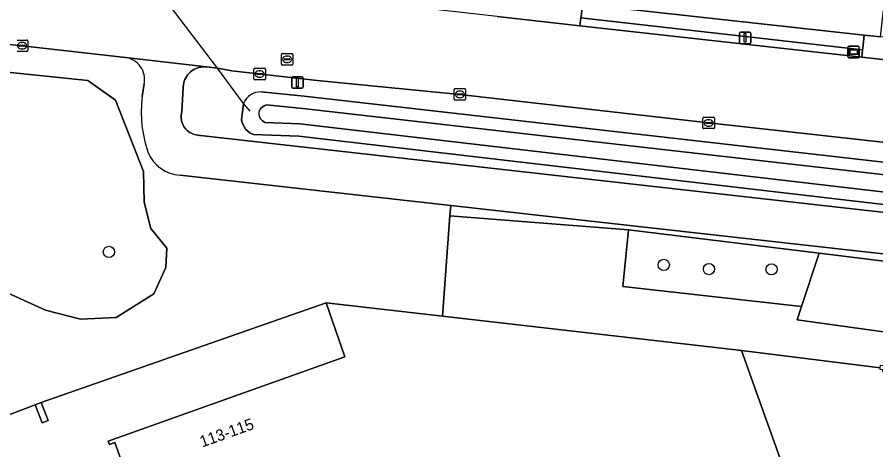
# Model space of a CAD drawing. Extents: x 161385 to 162589, y 388479 to 389756.
# Drawn here: x 162174.2 to 162249.2, y 388654.2 to 388691.9 of the extents above; entities that cross this region are included whole.
import ezdxf

# ---------------------------------------------------------------- set-up
doc = ezdxf.new("R2010")
doc.units = 0
for name, color, linetype in [('IMGEO_Berm_groen', 7, 'Continuous'), ('IMGEO_Boom', 7, 'Continuous'), ('IMGEO_Duiker', 7, 'Continuous'), ('IMGEO_Erf', 7, 'Continuous'), ('IMGEO_Fietspad_gesloten', 7, 'Continuous'), ('IMGEO_Groenvoorziening', 7, 'Continuous'), ('IMGEO_Kolk', 7, 'Continuous'), ('IMGEO_Lichtmast', 7, 'Continuous'), ('IMGEO_Oever', 7, 'Continuous'), ('IMGEO_Pand', 7, 'Continuous'), ('IMGEO_Pand_nummerreeks', 7, 'Continuous'), ('IMGEO_Rijbaan_lokaal_gesloten', 7, 'Continuous'), ('IMGEO_Rioolput', 7, 'Continuous'), ('IMGEO_Voetpad_open', 7, 'Continuous'), ('IMGEO_Waterloop', 7, 'Continuous'), ('IMGEO_Wegwijzer', 7, 'Continuous')]:
    doc.layers.add(name, color=color, linetype=linetype)

msp = doc.modelspace()

# ---------------------------------------------------------------- linework, layer by layer
at = {"layer": 'IMGEO_Berm_groen'}
for points in [[(162223.419, 388691.863), (162223.34, 388691.176), (162247.951, 388688.424), (162248.018, 388689.075)], [(162212.05, 388675.493), (162211.982, 388674.58), (162227.587, 388673.375), (162244.211, 388671.327), (162267.366, 388668.474), (162328.021, 388661.404), (162328.163, 388662.672), (162327.44, 388662.75), (162327.383, 388662.532), (162314.863, 388664.007)]]:
    msp.add_lwpolyline(points, close=True, dxfattribs=at)
for points in [[(162256.569, 388680.26), (162234.573, 388682.697), (162212.852, 388685.186), (162200.409, 388686.41), (162192.948, 388687.248), (162191.691, 388687.487), (162190.731, 388687.591), (162190.565, 388687.6), (162190.4, 388687.594), (162190.235, 388687.573), (162190.073, 388687.537), (162189.915, 388687.488), (162189.762, 388687.424), (162189.615, 388687.347), (162189.476, 388687.257), (162189.345, 388687.155), (162189.224, 388687.041), (162189.113, 388686.918), (162189.014, 388686.785), (162188.927, 388686.643), (162188.854, 388686.495), (162188.794, 388686.34), (162188.747, 388686.181), (162188.716, 388686.018), (162188.699, 388685.853), (162188.696, 388685.79), (162188.57, 388683.655), (162188.54, 388683.511), (162188.523, 388683.366), (162188.52, 388683.219), (162188.529, 388683.073), (162188.552, 388682.928), (162188.587, 388682.786), (162188.635, 388682.647), (162188.695, 388682.513), (162188.766, 388682.385), (162188.849, 388682.265), (162188.943, 388682.151), (162189.046, 388682.047), (162189.158, 388681.953), (162189.278, 388681.868), (162189.405, 388681.795), (162189.538, 388681.734), (162189.676, 388681.684), (162189.818, 388681.647), (162189.962, 388681.623), (162190.109, 388681.612), (162190.209, 388681.612), (162327.081, 388666.21)], [(162195.511, 388685.399), (162199.258, 388685.044), (162309.372, 388672.493), (162313.677, 388672.019)], [(162314.929, 388670.455), (162314.838, 388669.228), (162314.739, 388669.003), (162314.316, 388668.451), (162313.561, 388668.026), (162313.044, 388667.945), (162308.893, 388668.677), (162198.797, 388681.534), (162194.824, 388681.685), (162194.516, 388681.817), (162194.124, 388682.146), (162193.837, 388682.714), (162193.797, 388682.968), (162193.974, 388684.393)]]:
    msp.add_lwpolyline(points, dxfattribs=at)
msp.add_arc((162195.451, 388683.814), 1.587, 87.83194, 158.5793, dxfattribs=at)
at = {"layer": 'IMGEO_Boom'}
for centre in [(162182.211, 388671.44), (162230.659, 388670.305), (162234.598, 388669.941), (162240.061, 388669.921)]:
    msp.add_circle(centre, 0.489, dxfattribs=at)
at = {"layer": 'IMGEO_Duiker'}
msp.add_lwpolyline([(162194.552, 388683.711), (162193.974, 388684.393), (162191.691, 388687.487), (162185.651, 388695.455)], dxfattribs=at)
at = {"layer": 'IMGEO_Erf'}
for points in [[(162185.543, 388646.914), (162182.743, 388654.798), (162182.252, 388654.637), (162182.158, 388654.923), (162202.802, 388662.297), (162201.171, 388666.993), (162176.301, 388658.294), (162176.903, 388656.724), (162176.388, 388656.526), (162175.785, 388658.097), (162170.991, 388656.301), (162170.064, 388658.999), (162164.277, 388656.982), (162154.98, 388683.469), (162154.569, 388683.938), (162154.062, 388683.782), (162156.404, 388677.209), (162139.153, 388671.976), (162153.607, 388624.128)], [(162278.169, 388581.632), (162249.791, 388661.103), (162249.773, 388661.153), (162249.539, 388661.179), (162249.555, 388661.32), (162237.455, 388662.849), (162248.797, 388631.105)]]:
    msp.add_lwpolyline(points, dxfattribs=at)
at = {"layer": 'IMGEO_Fietspad_gesloten'}
for points in [[(162327.081, 388666.21), (162190.209, 388681.612), (162190.109, 388681.612), (162189.962, 388681.623), (162189.818, 388681.647), (162189.676, 388681.684), (162189.538, 388681.734), (162189.405, 388681.795), (162189.278, 388681.868), (162189.158, 388681.953), (162189.046, 388682.047), (162188.943, 388682.151), (162188.849, 388682.265), (162188.766, 388682.385), (162188.695, 388682.513), (162188.635, 388682.647), (162188.587, 388682.786), (162188.552, 388682.928), (162188.529, 388683.073), (162188.52, 388683.219), (162188.523, 388683.366), (162188.54, 388683.511), (162188.57, 388683.655), (162188.696, 388685.79), (162188.699, 388685.853), (162188.716, 388686.018), (162188.747, 388686.181), (162188.794, 388686.34), (162188.854, 388686.495), (162188.927, 388686.643), (162189.014, 388686.785), (162189.113, 388686.918), (162189.224, 388687.041), (162189.345, 388687.155), (162189.476, 388687.257), (162189.615, 388687.347), (162189.762, 388687.424), (162189.915, 388687.488), (162190.073, 388687.537), (162190.235, 388687.573), (162190.4, 388687.594), (162190.565, 388687.6), (162190.731, 388687.591), (162183.657, 388688.405)], [(162185.28, 388686.094), (162185.128, 388685.009)], [(162188.441, 388678.131), (162212.05, 388675.493), (162314.863, 388664.007), (162327.383, 388662.532), (162327.44, 388662.75), (162328.163, 388662.672), (162328.425, 388662.644)]]:
    msp.add_lwpolyline(points, dxfattribs=at)
for centre, radius, start, end in [((162183.403, 388686.501), 1.92, 347.74902, 82.4112), ((162195.589, 388683.618), 10.553, 172.42806, 199.06817), ((162188.627, 388681.366), 3.241, 201.64367, 266.70768)]:
    msp.add_arc(centre, radius, start, end, dxfattribs=at)
at = {"layer": 'IMGEO_Groenvoorziening'}
for points in [[(162249.57, 388690.204), (162249.919, 388693.319), (162223.633, 388696.259), (162223.374, 388693.364), (162223.587, 388693.331), (162223.557, 388693.066), (162248.149, 388690.348)], [(162164.533, 388675.08), (162172.104, 388668.423), (162176.667, 388666.349), (162179.722, 388665.557), (162182.852, 388665.708), (162186.133, 388667.782), (162187.189, 388670.082), (162187.264, 388671.779), (162185.869, 388673.476), (162185.303, 388675.776), (162185.228, 388678.454), (162182.776, 388684.676), (162180.363, 388686.411), (162171.048, 388687.354), (162167.504, 388687.618), (162164.223, 388686.562), (162163.648, 388686.001), (162162.196, 388681.874)], [(162266.988, 388662.085), (162242.291, 388665.501), (162242.681, 388666.67), (162227.085, 388668.43), (162227.587, 388673.375), (162211.982, 388674.58), (162211.331, 388665.832), (162237.455, 388662.849), (162249.555, 388661.32), (162249.582, 388661.569), (162250.099, 388661.511), (162324.031, 388653.194), (162323.903, 388652.051), (162326.935, 388651.71), (162327.291, 388654.887), (162309.928, 388656.723)], [(162242.681, 388666.67), (162244.211, 388671.327), (162227.587, 388673.375), (162227.085, 388668.43)], [(162266.988, 388662.085), (162309.928, 388656.723), (162327.291, 388654.887), (162328.021, 388661.404), (162267.366, 388668.474), (162244.211, 388671.327), (162242.681, 388666.67), (162242.291, 388665.501)]]:
    msp.add_lwpolyline(points, close=True, dxfattribs=at)
for points in [[(162183.657, 388688.405), (162174.63, 388689.431), (162165.201, 388690.414)], [(162171.048, 388687.354), (162180.363, 388686.411), (162182.776, 388684.676), (162185.228, 388678.454), (162185.303, 388675.776), (162185.869, 388673.476), (162187.264, 388671.779), (162187.189, 388670.082), (162186.133, 388667.782), (162182.852, 388665.708), (162179.722, 388665.557), (162176.667, 388666.349), (162172.104, 388668.423)], [(162185.128, 388685.009), (162185.28, 388686.094)], [(162170.991, 388656.301), (162175.785, 388658.097), (162176.301, 388658.294), (162201.171, 388666.993), (162211.331, 388665.832), (162211.982, 388674.58), (162212.05, 388675.493), (162188.441, 388678.131)]]:
    msp.add_lwpolyline(points, dxfattribs=at)
for centre, radius, start, end in [((162183.403, 388686.501), 1.92, 347.74902, 82.4112), ((162195.589, 388683.618), 10.553, 172.42806, 199.06817), ((162188.627, 388681.366), 3.241, 201.64367, 266.70768)]:
    msp.add_arc(centre, radius, start, end, dxfattribs=at)
at = {"layer": 'IMGEO_Kolk'}
for p, q in [((162174.204, 388689.93), (162175.056, 388689.93)), ((162174.617, 388689.71), (162174.642, 388689.71)), ((162175.13, 388689.856), (162175.13, 388689.004)), ((162175.056, 388688.93), (162174.204, 388688.93)), ((162174.388, 388689.424), (162174.388, 388689.436)), ((162174.826, 388689.387), (162174.428, 388689.387)), ((162174.431, 388689.473), (162174.829, 388689.473)), ((162174.64, 388689.15), (162174.615, 388689.15)), ((162174.872, 388689.436), (162174.872, 388689.424)), ((162194.948, 388687.47), (162195.8, 388687.47)), ((162194.873, 388686.544), (162194.873, 388687.396)), ((162195.132, 388686.964), (162195.132, 388686.976)), ((162195.57, 388686.927), (162195.172, 388686.927)), ((162195.175, 388687.013), (162195.573, 388687.013)), ((162195.384, 388686.69), (162195.359, 388686.69)), ((162195.361, 388687.25), (162195.386, 388687.25)), ((162195.616, 388686.976), (162195.616, 388686.964)), ((162195.874, 388687.396), (162195.874, 388686.544)), ((162195.8, 388686.47), (162194.948, 388686.47)), ((162212.35, 388684.76), (162212.35, 388685.612)), ((162212.425, 388685.686), (162213.277, 388685.686)), ((162212.609, 388685.18), (162212.609, 388685.192)), ((162212.652, 388685.229), (162213.05, 388685.229)), ((162212.838, 388685.466), (162212.863, 388685.466)), ((162213.093, 388685.192), (162213.093, 388685.18)), ((162213.351, 388685.612), (162213.351, 388684.76)), ((162213.277, 388684.686), (162212.425, 388684.686)), ((162213.047, 388685.143), (162212.649, 388685.143)), ((162212.861, 388684.906), (162212.836, 388684.906)), ((162234.072, 388682.27), (162234.072, 388683.122)), ((162234.147, 388683.196), (162234.999, 388683.196)), ((162234.56, 388682.976), (162234.585, 388682.976)), ((162235.073, 388683.122), (162235.073, 388682.27)), ((162234.999, 388682.196), (162234.147, 388682.196)), ((162234.331, 388682.69), (162234.331, 388682.702)), ((162234.769, 388682.653), (162234.371, 388682.653)), ((162234.374, 388682.739), (162234.772, 388682.739)), ((162234.583, 388682.416), (162234.558, 388682.416)), ((162234.815, 388682.702), (162234.815, 388682.69))]:
    msp.add_line(p, q, dxfattribs=at)
for points in [[(162174.204, 388689.93), (162175.056, 388689.93)], [(162175.13, 388689.856), (162175.13, 388689.004)], [(162175.056, 388688.93), (162174.204, 388688.93)], [(162194.948, 388687.47), (162195.8, 388687.47)], [(162194.873, 388686.544), (162194.873, 388687.396)], [(162195.874, 388687.396), (162195.874, 388686.544)], [(162195.8, 388686.47), (162194.948, 388686.47)], [(162212.35, 388684.76), (162212.35, 388685.612)], [(162212.425, 388685.686), (162213.277, 388685.686)], [(162213.351, 388685.612), (162213.351, 388684.76)], [(162213.277, 388684.686), (162212.425, 388684.686)], [(162234.072, 388682.27), (162234.072, 388683.122)], [(162234.147, 388683.196), (162234.999, 388683.196)], [(162235.073, 388683.122), (162235.073, 388682.27)], [(162234.999, 388682.196), (162234.147, 388682.196)]]:
    msp.add_lwpolyline(points, dxfattribs=at)
for centre, radius, start, end in [((162175.054, 388689.854), 0.0765, 1.55205, 88.44795), ((162175.054, 388689.854), 0.0765, 1.55205, 88.44795), ((162174.428, 388689.433), 0.0403, 85.87752, 175.75265), ((162174.425, 388689.423), 0.0366, 178.93798, 274.71019), ((162174.829, 388689.43), 0.043, 264.86636, 352.45326), ((162174.833, 388689.435), 0.0386, 1.73085, 96.63898), ((162175.054, 388689.006), 0.0765, 271.55205, 358.44795), ((162175.054, 388689.006), 0.0765, 271.55205, 358.44795), ((162194.95, 388687.394), 0.0765, 91.55205, 178.44795), ((162194.95, 388687.394), 0.0765, 91.55205, 178.44795), ((162195.798, 388687.394), 0.0765, 1.55205, 88.44795), ((162195.798, 388687.394), 0.0765, 1.55205, 88.44795), ((162195.172, 388686.973), 0.0403, 85.87752, 175.75265), ((162195.169, 388686.963), 0.0366, 178.93798, 274.71019), ((162195.573, 388686.97), 0.043, 264.86636, 352.45326), ((162195.577, 388686.975), 0.0386, 1.73085, 96.63898), ((162194.95, 388686.546), 0.0765, 181.55205, 268.44795), ((162194.95, 388686.546), 0.0765, 181.55205, 268.44795), ((162195.798, 388686.546), 0.0765, 271.55205, 358.44795), ((162195.798, 388686.546), 0.0765, 271.55205, 358.44795), ((162212.427, 388685.61), 0.0765, 91.55205, 178.44795), ((162212.427, 388685.61), 0.0765, 91.55205, 178.44795), ((162212.649, 388685.189), 0.0403, 85.87752, 175.75265), ((162212.646, 388685.179), 0.0366, 178.93798, 274.71019), ((162213.05, 388685.186), 0.043, 264.86636, 352.45326), ((162213.054, 388685.191), 0.0386, 1.73085, 96.63898), ((162213.275, 388685.61), 0.0765, 1.55205, 88.44795), ((162213.275, 388685.61), 0.0765, 1.55205, 88.44795), ((162212.427, 388684.762), 0.0765, 181.55205, 268.44795), ((162212.427, 388684.762), 0.0765, 181.55205, 268.44795), ((162213.275, 388684.762), 0.0765, 271.55205, 358.44795), ((162213.275, 388684.762), 0.0765, 271.55205, 358.44795), ((162234.149, 388683.12), 0.0765, 91.55205, 178.44795), ((162234.149, 388683.12), 0.0765, 91.55205, 178.44795), ((162234.997, 388683.12), 0.0765, 1.55205, 88.44795), ((162234.997, 388683.12), 0.0765, 1.55205, 88.44795), ((162234.149, 388682.272), 0.0765, 181.55205, 268.44795), ((162234.149, 388682.272), 0.0765, 181.55205, 268.44795), ((162234.371, 388682.699), 0.0403, 85.87752, 175.75265), ((162234.368, 388682.689), 0.0366, 178.93798, 274.71019), ((162234.772, 388682.696), 0.043, 264.86636, 352.45326), ((162234.776, 388682.701), 0.0386, 1.73085, 96.63898), ((162234.997, 388682.272), 0.0765, 271.55205, 358.44795), ((162234.997, 388682.272), 0.0765, 271.55205, 358.44795)]:
    msp.add_arc(centre, radius, start, end, dxfattribs=at)
for centre, major_axis, ratio, start_param, end_param in [((162174.616, 388689.43), (-0.387, 0.002), 0.722429, 4.712389, 7.853982), ((162174.641, 388689.43), (-0.39, 0.002), 0.717154, 1.570796, 4.712389), ((162195.36, 388686.97), (-0.387, 0.002), 0.722429, 4.712389, 7.853982), ((162195.385, 388686.97), (-0.39, 0.002), 0.717154, 1.570796, 4.712389), ((162212.837, 388685.186), (-0.387, 0.002), 0.722429, 4.712389, 7.853982), ((162212.862, 388685.186), (-0.39, 0.002), 0.717154, 1.570796, 4.712389), ((162234.559, 388682.696), (-0.387, 0.002), 0.722429, 4.712389, 7.853982), ((162234.584, 388682.696), (-0.39, 0.002), 0.717154, 1.570796, 4.712389)]:
    msp.add_ellipse(centre, major_axis=major_axis, ratio=ratio, start_param=start_param, end_param=end_param, dxfattribs=at)
at = {"layer": 'IMGEO_Lichtmast'}
for p, q in [((162237.254, 388689.71), (162237.254, 388690.51)), ((162237.254, 388690.51), (162237.254, 388689.71)), ((162237.354, 388690.61), (162238.144, 388690.61)), ((162238.144, 388690.61), (162237.354, 388690.61)), ((162238.244, 388690.51), (162238.244, 388689.71)), ((162238.244, 388689.71), (162238.244, 388690.51)), ((162238.144, 388689.61), (162237.354, 388689.61)), ((162237.354, 388689.61), (162238.144, 388689.61)), ((162198.274, 388686.715), (162199.064, 388686.715)), ((162199.064, 388686.715), (162198.274, 388686.715)), ((162198.174, 388685.815), (162198.174, 388686.615)), ((162198.174, 388686.615), (162198.174, 388685.815)), ((162199.164, 388686.615), (162199.164, 388685.815)), ((162199.164, 388685.815), (162199.164, 388686.615)), ((162199.064, 388685.715), (162198.274, 388685.715)), ((162198.274, 388685.715), (162199.064, 388685.715))]:
    msp.add_line(p, q, dxfattribs=at)
for points in [[(162237.674, 388690.485), (162237.824, 388690.485), (162237.824, 388689.735), (162237.674, 388689.735), (162237.674, 388690.485)], [(162198.594, 388686.59), (162198.744, 388686.59), (162198.744, 388685.84), (162198.594, 388685.84), (162198.594, 388686.59)]]:
    msp.add_lwpolyline(points, dxfattribs=at)
for centre, start, end in [((162237.354, 388690.51), 90, 180), ((162237.354, 388690.51), 90, 180), ((162238.144, 388690.51), 0, 90), ((162238.144, 388690.51), 360, 90), ((162237.354, 388689.71), 180, 270), ((162237.354, 388689.71), 180, 270), ((162238.144, 388689.71), 270, 0), ((162238.144, 388689.71), 270, 0), ((162198.274, 388686.615), 90, 180), ((162198.274, 388686.615), 90, 180), ((162199.064, 388686.615), 0, 90), ((162199.064, 388686.615), 360, 90), ((162198.274, 388685.815), 180, 270), ((162198.274, 388685.815), 180, 270), ((162199.064, 388685.815), 270, 0), ((162199.064, 388685.815), 270, 0)]:
    msp.add_arc(centre, 0.1, start, end, dxfattribs=at)
at = {"layer": 'IMGEO_Oever'}
for points in [[(162199.258, 388685.044), (162195.511, 388685.399)], [(162313.677, 388672.019), (162309.372, 388672.493), (162199.258, 388685.044)], [(162193.974, 388684.393), (162193.797, 388682.968), (162193.837, 388682.714), (162194.124, 388682.146), (162194.516, 388681.817), (162194.824, 388681.685), (162198.797, 388681.534), (162308.893, 388668.677), (162313.044, 388667.945), (162313.561, 388668.026), (162314.316, 388668.451), (162314.739, 388669.003), (162314.838, 388669.228), (162314.929, 388670.455)], [(162195.481, 388683.991), (162195.754, 388684.173), (162195.97, 388684.262), (162199.145, 388683.962), (162309.251, 388671.412), (162312.727, 388671.029)], [(162312.207, 388669.198), (162309.051, 388669.754), (162198.881, 388682.62), (162195.82, 388682.736), (162195.633, 388682.868), (162195.481, 388683.01), (162195.347, 388683.225)]]:
    msp.add_lwpolyline(points, dxfattribs=at)
for centre, radius, start, end in [((162195.451, 388683.814), 1.587, 87.83194, 158.5793), ((162196.019, 388683.502), 0.727, 137.72091, 202.43386)]:
    msp.add_arc(centre, radius, start, end, dxfattribs=at)
at = {"layer": 'IMGEO_Pand'}
for points in [[(162211.331, 388665.832), (162201.171, 388666.993), (162202.802, 388662.297), (162182.158, 388654.923), (162182.252, 388654.637), (162182.743, 388654.798), (162185.543, 388646.914), (162180.831, 388645.223), (162180.558, 388645.977), (162180.164, 388645.887), (162182.655, 388638.891), (162184.222, 388634.491), (162188.677, 388621.975), (162192.555, 388611.083), (162248.797, 388631.105), (162237.455, 388662.849)], [(162175.785, 388658.097), (162176.388, 388656.526), (162176.903, 388656.724), (162176.301, 388658.294)]]:
    msp.add_lwpolyline(points, close=True, dxfattribs=at)
at = {"layer": 'IMGEO_Rijbaan_lokaal_gesloten'}
for points in [[(162353.423, 388676.578), (162317.536, 388680.643), (162316.844, 388680.72), (162297.525, 388682.881), (162285.793, 388684.193), (162285.607, 388684.214), (162265.796, 388686.429), (162255.908, 388687.535), (162247.951, 388688.424), (162223.34, 388691.176), (162216.117, 388691.984), (162185.651, 388695.455), (162184.144, 388695.622), (162173.399, 388696.814)], [(162162.995, 388690.57), (162164.811, 388690.455), (162165.201, 388690.414), (162174.63, 388689.431), (162183.657, 388688.405), (162190.731, 388687.591), (162191.691, 388687.487), (162192.948, 388687.248), (162200.409, 388686.41), (162212.852, 388685.186), (162234.573, 388682.697), (162256.569, 388680.26), (162277.429, 388677.907), (162297.925, 388675.602), (162319.739, 388673.126), (162319.871, 388673.113), (162320.835, 388672.971), (162352.961, 388669.418)]]:
    msp.add_lwpolyline(points, dxfattribs=at)
at = {"layer": 'IMGEO_Rioolput'}
for p, q in [((162197.271, 388687.824), (162197.271, 388688.676)), ((162197.346, 388688.75), (162198.198, 388688.75)), ((162197.53, 388688.244), (162197.53, 388688.256)), ((162197.968, 388688.207), (162197.57, 388688.207)), ((162197.573, 388688.293), (162197.971, 388688.293)), ((162197.759, 388688.53), (162197.784, 388688.53)), ((162198.014, 388688.256), (162198.014, 388688.244)), ((162198.272, 388688.676), (162198.272, 388687.824)), ((162198.198, 388687.75), (162197.346, 388687.75)), ((162197.782, 388687.97), (162197.757, 388687.97))]:
    msp.add_line(p, q, dxfattribs=at)
for points in [[(162197.271, 388687.824), (162197.271, 388688.676)], [(162197.346, 388688.75), (162198.198, 388688.75)], [(162198.272, 388688.676), (162198.272, 388687.824)], [(162198.198, 388687.75), (162197.346, 388687.75)]]:
    msp.add_lwpolyline(points, dxfattribs=at)
for centre, radius, start, end in [((162197.348, 388688.674), 0.0765, 91.55205, 178.44795), ((162197.348, 388688.674), 0.0765, 91.55205, 178.44795), ((162197.57, 388688.253), 0.0403, 85.87752, 175.75265), ((162197.567, 388688.243), 0.0366, 178.93798, 274.71019), ((162197.971, 388688.25), 0.043, 264.86636, 352.45326), ((162197.975, 388688.255), 0.0386, 1.73085, 96.63898), ((162198.196, 388688.674), 0.0765, 1.55205, 88.44795), ((162198.196, 388688.674), 0.0765, 1.55205, 88.44795), ((162197.348, 388687.826), 0.0765, 181.55205, 268.44795), ((162197.348, 388687.826), 0.0765, 181.55205, 268.44795), ((162198.196, 388687.826), 0.0765, 271.55205, 358.44795), ((162198.196, 388687.826), 0.0765, 271.55205, 358.44795)]:
    msp.add_arc(centre, radius, start, end, dxfattribs=at)
for centre, major_axis, ratio, start_param, end_param in [((162197.758, 388688.25), (-0.387, 0.002), 0.722429, 4.712389, 7.853982), ((162197.783, 388688.25), (-0.39, 0.002), 0.717154, 1.570796, 4.712389)]:
    msp.add_ellipse(centre, major_axis=major_axis, ratio=ratio, start_param=start_param, end_param=end_param, dxfattribs=at)
at = {"layer": 'IMGEO_Voetpad_open'}
msp.add_lwpolyline([(162216.117, 388691.984), (162223.34, 388691.176), (162223.419, 388691.863), (162223.432, 388691.98), (162223.557, 388693.066), (162223.587, 388693.331), (162223.374, 388693.364), (162216.358, 388694.266), (162214.345, 388694.525), (162214.313, 388694.428)], dxfattribs=at)
for points in [[(162223.419, 388691.863), (162248.018, 388689.075), (162248.034, 388689.229), (162248.149, 388690.348), (162223.557, 388693.066), (162223.432, 388691.98)], [(162248.149, 388690.348), (162248.034, 388689.229), (162248.018, 388689.075), (162247.951, 388688.424), (162255.908, 388687.535), (162255.966, 388688.342), (162256.055, 388689.574), (162254.13, 388689.743), (162249.57, 388690.204)]]:
    msp.add_lwpolyline(points, close=True, dxfattribs=at)
at = {"layer": 'IMGEO_Waterloop'}
for points in [[(162195.97, 388684.262), (162195.754, 388684.173), (162195.481, 388683.991)], [(162312.727, 388671.029), (162309.251, 388671.412), (162199.145, 388683.962), (162195.97, 388684.262)], [(162195.347, 388683.225), (162195.481, 388683.01), (162195.633, 388682.868), (162195.82, 388682.736), (162198.881, 388682.62), (162309.051, 388669.754), (162312.207, 388669.198)]]:
    msp.add_lwpolyline(points, dxfattribs=at)
msp.add_arc((162196.019, 388683.502), 0.727, 137.72091, 202.43386, dxfattribs=at)
at = {"layer": 'IMGEO_Wegwijzer'}
for p, q in [((162246.737, 388688.49), (162246.737, 388689.29)), ((162246.737, 388689.29), (162246.737, 388688.49)), ((162246.837, 388689.39), (162247.627, 388689.39)), ((162247.627, 388689.39), (162246.837, 388689.39)), ((162247.727, 388689.29), (162247.727, 388688.49)), ((162247.727, 388688.49), (162247.727, 388689.29)), ((162247.627, 388688.39), (162246.837, 388688.39)), ((162246.837, 388688.39), (162247.627, 388688.39))]:
    msp.add_line(p, q, dxfattribs=at)
for points in [[(162246.838, 388689.122), (162247.626, 388689.122), (162247.626, 388688.658), (162246.838, 388688.658), (162246.838, 388689.122)], [(162246.903, 388689.057), (162246.903, 388688.723), (162247.561, 388688.723), (162247.561, 388689.057), (162246.903, 388689.057)]]:
    msp.add_lwpolyline(points, dxfattribs=at)
for centre, start, end in [((162246.837, 388689.29), 90, 180), ((162246.837, 388689.29), 90, 180), ((162247.627, 388689.29), 0, 90), ((162247.627, 388689.29), 360, 90), ((162246.837, 388688.49), 180, 270), ((162246.837, 388688.49), 180, 270), ((162247.627, 388688.49), 270, 0), ((162247.627, 388688.49), 270, 0)]:
    msp.add_arc(centre, 0.1, start, end, dxfattribs=at)

# ---------------------------------------------------------------- texts
at = {"layer": 'IMGEO_Pand_nummerreeks'}
msp.add_text('113-115', height=1, rotation=19.65803, dxfattribs=at).set_placement((162190.349, 388654.366))

doc.saveas('drawing.dxf')
